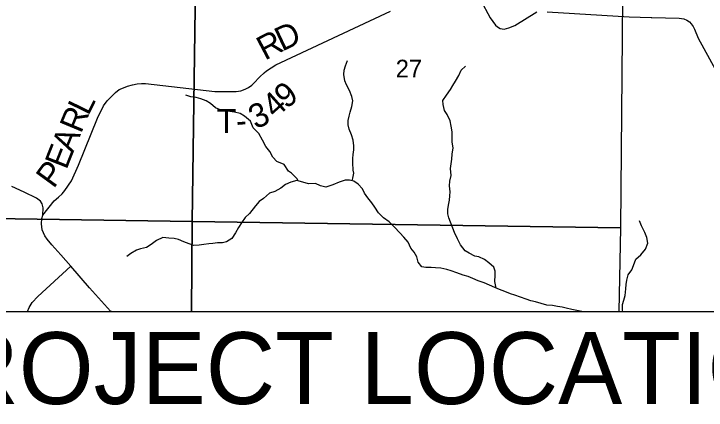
# Model space of a CAD drawing. Extents: x -20.5 to 34, y -66 to 23.9.
# Drawn here: x 6.523 to 8.16, y 18.93 to 19.867 of the extents above; entities that cross this region are included whole.
import ezdxf

# ---------------------------------------------------------------- set-up
doc = ezdxf.new("R2010")
doc.units = 0
for name, color, linetype in [('GM_X_County_Road_Text', 7, 'Continuous'), ('GM_X_County_Text', 7, 'Continuous'), ('GM_X_Minor_Lake', 7, 'Continuous'), ('GM_X_Minor_River_Text', 7, 'Continuous'), ('GM_X_Section_Text', 7, 'Continuous'), ('GM_X_State_Route', 7, 'Continuous'), ('GM_X_Township_Road', 7, 'Continuous'), ('GM_X_Township_Text', 7, 'Continuous'), ('SH_Text', 7, 'Continuous')]:
    doc.layers.add(name, color=color, linetype=linetype)

msp = doc.modelspace()

# ---------------------------------------------------------------- linework, layer by layer
at = {"layer": 'GM_X_County_Text'}
for points in [[(7.6261, 19.9008), (7.6494, 19.8574), (7.6619, 19.8405), (7.6666, 19.8361), (7.6731, 19.8324), (7.678, 19.8313), (7.6827, 19.8306), (7.6936, 19.8339), (7.7076, 19.8399), (7.7596, 19.8718)], [(6.5911, 19.3913), (6.6184, 19.4248), (6.6285, 19.4336), (6.6372, 19.4414), (6.6432, 19.4492), (6.6594, 19.4721), (6.6757, 19.509), (6.7203, 19.6204), (6.7346, 19.6496), (6.7437, 19.6615), (6.7547, 19.6728), (6.763, 19.6811), (6.7719, 19.688), (6.7822, 19.6925), (6.7915, 19.696), (6.8036, 19.6993), (6.8142, 19.7017), (6.8248, 19.7024), (6.834, 19.7025), (6.9977, 19.6837), (7.0335, 19.6831), (7.0483, 19.6837), (7.0597, 19.6853), (7.0697, 19.6887), (7.0776, 19.6929), (7.0855, 19.6981), (7.0899, 19.7022), (7.1044, 19.7185), (7.1147, 19.728), (7.1201, 19.7325), (7.1423, 19.7463), (7.4133, 19.8732)], [(7.7839, 19.8722), (7.9782, 19.86), (8.0303, 19.8587), (8.0316, 19.8586)], [(8.0316, 19.8586), (8.0967, 19.857), (8.1076, 19.8551), (8.1147, 19.8524), (8.1212, 19.8481), (8.1251, 19.8438), (8.1296, 19.8369), (8.133, 19.8307), (8.141, 19.8099), (8.1817, 19.7362)]]:
    msp.add_lwpolyline(points, dxfattribs=at)
at = {"layer": 'GM_X_Minor_Lake'}
for points in [[(5.9663, 20.3996), (6.9585, 20.3868), (6.9446, 19.3763), (5.9493, 19.3913), (5.9508, 19.4767)], [(6.9585, 20.3868), (7.9662, 20.3576), (7.9573, 19.3612), (6.9446, 19.3763)]]:
    msp.add_lwpolyline(points, close=True, dxfattribs=at)
for points in [[(6.9358, 18.3792), (6.9356, 18.3607), (5.9313, 18.3709), (5.9332, 18.4574), (5.9493, 19.3913), (6.9446, 19.3763), (6.9427, 19.1628)], [(6.9427, 19.1628), (6.9446, 19.3763), (7.9573, 19.3612), (7.9541, 19.1628)]]:
    msp.add_lwpolyline(points, dxfattribs=at)
at = {"layer": 'GM_X_Minor_River_Text'}
for points in [[(7.3254, 19.4976), (7.3244, 19.515), (7.3246, 19.5249), (7.3256, 19.5344), (7.3265, 19.5454), (7.3271, 19.5553), (7.325, 19.5685), (7.3214, 19.5806), (7.3158, 19.5946), (7.3134, 19.6048), (7.3136, 19.615), (7.3161, 19.6249), (7.3182, 19.6344), (7.3225, 19.6478), (7.3242, 19.6611), (7.3225, 19.6713), (7.3166, 19.6856), (7.3095, 19.6992), (7.3059, 19.709), (7.3034, 19.7237), (7.3044, 19.7336), (7.3069, 19.7439), (7.3116, 19.7569)], [(7.5558, 19.5016), (7.5585, 19.5234), (7.5598, 19.5356), (7.5615, 19.55), (7.5594, 19.5637), (7.5591, 19.5758), (7.5593, 19.5879), (7.5568, 19.6016), (7.5551, 19.6144), (7.5476, 19.6287), (7.541, 19.6389), (7.5381, 19.6525), (7.5376, 19.6623), (7.5457, 19.675), (7.5554, 19.688), (7.5609, 19.6976), (7.5676, 19.7076), (7.5749, 19.721), (7.5808, 19.7336), (7.5913, 19.7436)], [(7.1725, 19.495), (7.1623, 19.5108), (7.1448, 19.5177), (7.1351, 19.5282), (7.1284, 19.5414), (7.1191, 19.5537), (7.1105, 19.568), (7.1019, 19.5842), (7.0891, 19.5976), (7.0828, 19.6131), (7.0685, 19.625), (7.0578, 19.6316), (7.0448, 19.6345), (7.0334, 19.6358), (7.022, 19.6367), (7.0094, 19.6411), (6.9999, 19.6451), (6.9875, 19.6548), (6.9776, 19.661), (6.9649, 19.6665), (6.9539, 19.6694), (6.9417, 19.6711), (6.9295, 19.675)], [(7.1955, 19.472), (7.1926, 19.4772), (7.1795, 19.4902), (7.1725, 19.495)], [(7.3229, 19.4722), (7.3242, 19.4788), (7.3267, 19.4906), (7.3254, 19.4976)], [(7.6637, 19.2184), (7.6602, 19.2342), (7.6615, 19.2487), (7.6613, 19.2582), (7.6582, 19.268), (7.6459, 19.278), (7.6363, 19.2859), (7.6226, 19.2925), (7.6127, 19.2942), (7.5998, 19.3009), (7.5902, 19.3068), (7.579, 19.3206), (7.572, 19.3353), (7.5653, 19.35), (7.561, 19.3602), (7.5555, 19.3742), (7.5519, 19.3843), (7.5495, 19.3942), (7.549, 19.4044), (7.5507, 19.4147), (7.5528, 19.4268), (7.5542, 19.4367), (7.5548, 19.4462), (7.5534, 19.4602), (7.5536, 19.4716), (7.5572, 19.4846), (7.5558, 19.5016)], [(7.8659, 19.1628), (7.8546, 19.1651), (7.8425, 19.1676), (7.8292, 19.1712), (7.8193, 19.1733), (7.8087, 19.175), (7.7965, 19.1771), (7.7833, 19.1781), (7.77, 19.1817), (7.7563, 19.1856), (7.7456, 19.1885), (7.7342, 19.1925), (7.7213, 19.1972), (7.708, 19.202), (7.6973, 19.2048), (7.6844, 19.2107), (7.6715, 19.2151), (7.6604, 19.2198), (7.6475, 19.2257), (7.6349, 19.2308), (7.6212, 19.2359), (7.6082, 19.2414), (7.5972, 19.2462), (7.5854, 19.2494), (7.5702, 19.2549), (7.5569, 19.2592), (7.5466, 19.2621), (7.5329, 19.2653), (7.5201, 19.2663), (7.5098, 19.2669), (7.497, 19.2675), (7.4875, 19.2688), (7.479, 19.2797), (7.4758, 19.2922), (7.4699, 19.3035), (7.4615, 19.3132), (7.4552, 19.3271), (7.4448, 19.3391), (7.4356, 19.3488), (7.4232, 19.3623), (7.4102, 19.3754), (7.3968, 19.3843), (7.3856, 19.3966), (7.3767, 19.4101), (7.3698, 19.4199), (7.3597, 19.4319), (7.352, 19.4432), (7.3477, 19.453), (7.3369, 19.4645), (7.3266, 19.4712), (7.3163, 19.4741), (7.3065, 19.4739), (7.2918, 19.4692), (7.2775, 19.4625), (7.261, 19.4573), (7.2481, 19.4605), (7.2362, 19.4661), (7.22, 19.4647), (7.2063, 19.469), (7.1919, 19.473), (7.1775, 19.469), (7.1651, 19.4631), (7.1539, 19.4546), (7.1397, 19.4468), (7.1276, 19.4428), (7.1131, 19.4301), (7.1033, 19.4235), (7.094, 19.4131), (7.0803, 19.3947), (7.0702, 19.3854), (7.0613, 19.3731), (7.0539, 19.3616), (7.0469, 19.349), (7.038, 19.336), (7.0257, 19.3278), (7.0159, 19.3258), (7.0045, 19.3252), (6.9936, 19.3243), (6.9838, 19.323), (6.972, 19.3217), (6.9611, 19.32), (6.9482, 19.3191), (6.9376, 19.3231), (6.9246, 19.3282), (6.9125, 19.3333), (6.9015, 19.3354), (6.8889, 19.3367), (6.8753, 19.3381), (6.8603, 19.331), (6.8472, 19.3217), (6.8363, 19.3143), (6.8224, 19.3115), (6.8126, 19.3079), (6.7994, 19.3005), (6.7897, 19.2931)], [(7.9632, 19.1628), (7.9624, 19.1659), (7.9626, 19.18), (7.9655, 19.1895), (7.9683, 19.2013), (7.97, 19.2165), (7.9713, 19.2271), (7.9723, 19.237), (7.9759, 19.25), (7.9844, 19.2615), (7.9881, 19.2721), (7.9939, 19.2866), (8.0058, 19.2974), (8.0166, 19.3109), (8.0221, 19.3246), (8.02, 19.3382), (8.0156, 19.3503), (8.0074, 19.3657), (8.0023, 19.3778)]]:
    msp.add_lwpolyline(points, dxfattribs=at)
at = {"layer": 'GM_X_State_Route'}
msp.add_lwpolyline([(6.5547, 19.1628), (6.5592, 19.1725), (6.566, 19.1846), (6.5791, 19.1985), (6.6574, 19.27)], dxfattribs=at)
at = {"layer": 'GM_X_Township_Road'}
msp.add_lwpolyline([(6.7534, 19.1628), (6.7512, 19.1641), (6.7018, 19.2193), (6.6574, 19.27), (6.6336, 19.2975), (6.6126, 19.3207), (6.6011, 19.3342), (6.5963, 19.342), (6.5897, 19.3561), (6.5882, 19.3706), (6.5891, 19.3833), (6.5911, 19.3913), (6.5918, 19.4086), (6.5897, 19.4174), (6.5855, 19.424), (6.5765, 19.4309), (6.5471, 19.4451), (6.5179, 19.4588)], dxfattribs=at)
at = {"layer": 'SH_Text'}
msp.add_lwpolyline([(6.2064, 19.1628), (8.3774, 19.1628), (8.3774, 18.3792), (6.2064, 18.3792)], close=True, dxfattribs=at)

# ---------------------------------------------------------------- texts
at = {"layer": 'GM_X_County_Road_Text'}
msp.add_text('Creek', height=0.0947, rotation=36.301, dxfattribs=at).set_placement((6.3146, 19.819))
at = {"layer": 'GM_X_Section_Text'}
for s, rotation, p in [('D', 25.3398, (7.1572, 19.7775)), ('R', 27.7608, (7.1165, 19.7561)), ('9', 37.8535, (7.1666, 19.6407)), ('4', 41.8544, (7.1413, 19.6181)), ('L', 64.008, (6.699, 19.6246)), ('3', 25.5545, (7.0951, 19.5932)), ('R', 67.4064, (6.6815, 19.5823)), ('T', 359.6893, (7.0023, 19.5855)), ('-', 4.5863, (7.0501, 19.5855)), ('A', 67.7284, (6.6626, 19.5361)), ('E', 68.441, (6.647, 19.4967)), ('P', 53.887, (6.6168, 19.452))]:
    msp.add_text(s, height=0.0568, rotation=rotation, dxfattribs=at).set_placement(p)
at = {"layer": 'GM_X_Township_Text'}
msp.add_text('27', height=0.04186, rotation=0, dxfattribs=at).set_placement((7.426, 19.7167))
at = {"layer": 'SH_Text'}
msp.add_text('PROJECT LOCATION ', height=0.17, dxfattribs=at).set_placement((6.2187, 18.9442))

doc.saveas('drawing.dxf')
